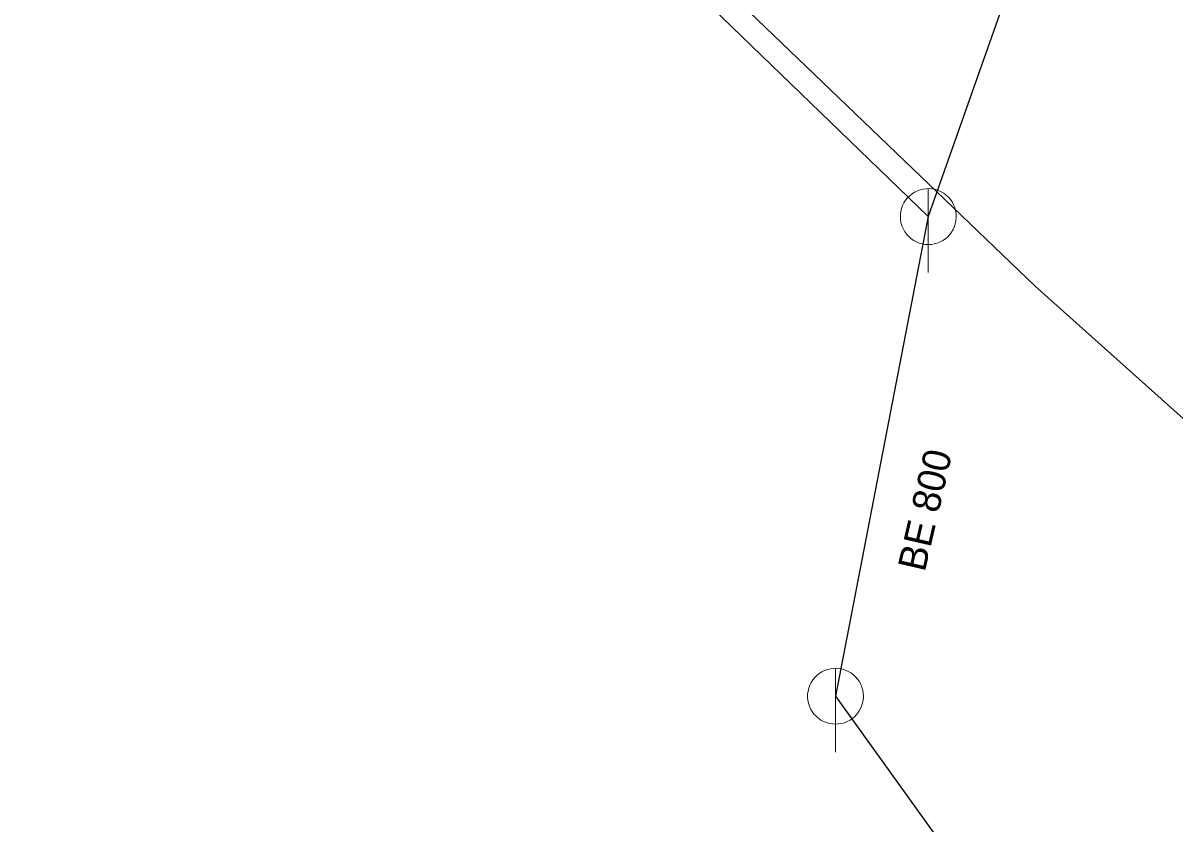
# Model space of a CAD drawing. Extents: x -807203 to -805207, y -993656 to -992505.
# Drawn here: x -805980.27 to -805939.05, y -993351.99 to -993323.34 of the extents above; entities that cross this region are included whole.
import ezdxf

# ---------------------------------------------------------------- set-up
doc = ezdxf.new("R2010")
doc.units = 0
doc.header["$LTSCALE"] = 0.4
for name, color, linetype, lineweight in [('1', 7, 'Continuous', 13), ('11', 7, 'Continuous', 13), ('14', 7, 'Continuous', 25), ('17', 7, 'Continuous', 25), ('22', 7, 'Continuous', 13)]:
    doc.layers.add(name, color=color, linetype=linetype, lineweight=lineweight)

msp = doc.modelspace()

# ---------------------------------------------------------------- linework, layer by layer
at = {"layer": '11'}
msp.add_line((-805962.21, -993316.399), (-805947.879, -993330.26), dxfattribs=at)
at = {"layer": '14'}
for p, q in [((-805943.489, -993317.82), (-805947.879, -993330.26)), ((-805947.879, -993330.26), (-805951.2, -993347.419)), ((-805951.2, -993347.419), (-805939.8, -993363.25))]:
    msp.add_line(p, q, dxfattribs=at)
at = {"layer": '17'}
msp.add_lwpolyline([(-805980.27, -993297.811), (-805964.539, -993313.096), (-805944.059, -993332.754), (-805925.796, -993349.072), (-805905.688, -993366.883), (-805894.556, -993375.978), (-805881.298, -993386.71), (-805877.651, -993389.561), (-805871.269, -993394.798), (-805850.666, -993411.467), (-805839.3, -993421.037), (-805830.275, -993428.564)], dxfattribs=at)
at = {"layer": '22'}
for p, q in [((-805947.879, -993332.26), (-805947.878, -993329.26)), ((-805951.2, -993349.419), (-805951.199, -993346.419))]:
    msp.add_line(p, q, dxfattribs=at)
for points in [[(-805946.879, -993330.26), (-805946.884, -993330.151), (-805946.902, -993330.043), (-805946.932, -993329.937), (-805946.972, -993329.836), (-805947.024, -993329.739), (-805947.086, -993329.649), (-805947.158, -993329.566), (-805947.238, -993329.492), (-805947.326, -993329.426), (-805947.42, -993329.371), (-805947.52, -993329.326), (-805947.625, -993329.293), (-805947.732, -993329.271), (-805947.841, -993329.261), (-805947.951, -993329.263), (-805948.059, -993329.277), (-805948.166, -993329.302), (-805948.269, -993329.339), (-805948.367, -993329.388), (-805948.459, -993329.446), (-805948.545, -993329.515), (-805948.622, -993329.592), (-805948.691, -993329.678), (-805948.75, -993329.77), (-805948.798, -993329.868), (-805948.835, -993329.971), (-805948.861, -993330.078), (-805948.875, -993330.186), (-805948.878, -993330.296), (-805948.868, -993330.405), (-805948.847, -993330.512), (-805948.813, -993330.616), (-805948.769, -993330.716), (-805948.714, -993330.811), (-805948.648, -993330.899), (-805948.574, -993330.979), (-805948.491, -993331.051), (-805948.401, -993331.113), (-805948.305, -993331.165), (-805948.203, -993331.206), (-805948.098, -993331.236), (-805947.99, -993331.254), (-805947.88, -993331.26), (-805947.771, -993331.254), (-805947.663, -993331.236), (-805947.558, -993331.207), (-805947.456, -993331.166), (-805947.359, -993331.114), (-805947.269, -993331.052), (-805947.186, -993330.981), (-805947.111, -993330.901), (-805947.046, -993330.813), (-805946.99, -993330.719), (-805946.946, -993330.619), (-805946.912, -993330.515), (-805946.89, -993330.407), (-805946.88, -993330.298)], [(-805950.2, -993347.419), (-805950.205, -993347.31), (-805950.223, -993347.202), (-805950.253, -993347.096), (-805950.293, -993346.995), (-805950.345, -993346.898), (-805950.407, -993346.808), (-805950.479, -993346.725), (-805950.559, -993346.651), (-805950.647, -993346.585), (-805950.741, -993346.53), (-805950.841, -993346.485), (-805950.946, -993346.452), (-805951.053, -993346.43), (-805951.162, -993346.42), (-805951.272, -993346.422), (-805951.38, -993346.436), (-805951.487, -993346.461), (-805951.59, -993346.498), (-805951.688, -993346.547), (-805951.78, -993346.605), (-805951.866, -993346.674), (-805951.943, -993346.751), (-805952.012, -993346.837), (-805952.071, -993346.929), (-805952.119, -993347.027), (-805952.156, -993347.13), (-805952.182, -993347.237), (-805952.196, -993347.345), (-805952.199, -993347.455), (-805952.189, -993347.564), (-805952.168, -993347.671), (-805952.134, -993347.775), (-805952.09, -993347.875), (-805952.035, -993347.97), (-805951.969, -993348.058), (-805951.895, -993348.138), (-805951.812, -993348.21), (-805951.722, -993348.272), (-805951.626, -993348.324), (-805951.524, -993348.365), (-805951.419, -993348.395), (-805951.311, -993348.413), (-805951.201, -993348.419), (-805951.092, -993348.413), (-805950.984, -993348.395), (-805950.879, -993348.366), (-805950.777, -993348.325), (-805950.68, -993348.273), (-805950.59, -993348.211), (-805950.507, -993348.14), (-805950.432, -993348.06), (-805950.367, -993347.972), (-805950.311, -993347.878), (-805950.267, -993347.778), (-805950.233, -993347.674), (-805950.211, -993347.566), (-805950.201, -993347.457)]]:
    msp.add_lwpolyline(points, close=True, dxfattribs=at)

# ---------------------------------------------------------------- texts
at = {"layer": '1'}
msp.add_text('BE 800', height=1, rotation=77, dxfattribs=at).set_placement((-805948.006, -993343.005))

doc.saveas('drawing.dxf')
